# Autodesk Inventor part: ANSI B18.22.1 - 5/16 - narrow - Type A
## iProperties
Comments: To add or edit properties for Autodesk Inventor files, use iProperties.
Created: 2005-06
Part Number: ANSI B18.22.1 - 5/16 - narrow - Type A
Vendor: Autodesk Inc.
Document SubType Name: Modeling
Designer: John Blackburn
Material: Default
Description: Washer A
Standard: ANSI B18.22.1
Alert: To add or edit properties for Autodesk Inventor files, use iProperties.
Control State: 0
Master: False
Checked Out: False
Shininess: 64.0
Length Units: 11272
Angle Units: 11279
Time Units: 11290
Mass Units: 11286
Length Display Precision: 3
Angle Display Precision: 2
Compacted: True
Classification: un/spsc 31161807
Density: 0.0
Volumn: 0.0
Area: 0.0
PropertySet Name: Model Information
Author: John Blackburn
Revision Number: 8
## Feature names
1. Body [Extrusion]
